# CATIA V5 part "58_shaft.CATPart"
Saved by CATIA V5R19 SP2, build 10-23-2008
Part number: 58_shaft
Bounding box of the stored display mesh (mm): x -9.462 to 9.462, y 130.9 to 149.824, z 44.259 to 64.259
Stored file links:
  C:\Documents and Settings\anizard\Bureau\13\58_shaft.CATPart
  C:\Program Files (x86)\Dassault Systemes\B19\intel_a\reffiles\standard\MetricThickPitch.txt
  C:\Documents and Settings\anizard\Bureau\13\anizard.CATProduct
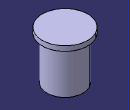
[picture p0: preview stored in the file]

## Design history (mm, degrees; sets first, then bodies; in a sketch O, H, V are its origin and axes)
Set1
  Line1: linked copy from another document
  Point1: linked copy from another document
  Plane1: linked copy from another document
  Point2: linked copy from another document
  Plane2: linked copy from another document
Body1 (main body)
  Sketch1 on yz-plane, origin (0, 0, 0), H (0, 1, 0), V (0, 0, 1)
    line L1 (149.8619, 64.2594) -> (149.8619, 62.2594)
    line L2 (149.8619, 62.2594) -> (147.8619, 62.2594)
    line L3 (147.8619, 62.2594) -> (147.8619, 44.2594)
    line L4 (147.8619, 44.2594) -> (140.3619, 44.2594)
    line L5 (140.3619, 44.2594) -> (140.3619, 64.2594)
    line L6 (140.3619, 64.2594) -> (149.8619, 64.2594)
    reference projected line E1 (140.3619, -361.5269) -> (140.3619, 18.4731) from Line1
    reference intersected line E2 through (0, 44.2594) direction (-1, 0) from Plane1
    reference projected point E3 (147.8619, 44.2594) from Point2
    reference intersected line E4 through (0, 62.2594) direction (-1, 0) from Plane2
    distance L6 L2 = 2
    distance L1 L3 = 2
    vertical: L1 V, L3 V, L5 V
    horizontal: L2 H, L4 H
    coincidence: L5 E1, E2 L4, L3 E3, L2 E4
  Shaft1: profile Sketch1, axis Line1, angle 360
  Sketch2 on face of Shaft1 from Sketch1.L4, origin (0, 0, 44.2594), H (1, 0, 0), V (0, -1, 0)
    point P1 (0, -140.3619)
    reference projected point E1 (0, -140.3619) from Point1
    coincidence: E1 P1
  Hole1: placed by Sketch2, at (0, 140.3619, 44.2594) direction (0, 0, 1), diameter 4.134, depth 11, V-bottom angle 120, threaded "M5", thread diameter 5, thread depth 9, pitch 0.8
